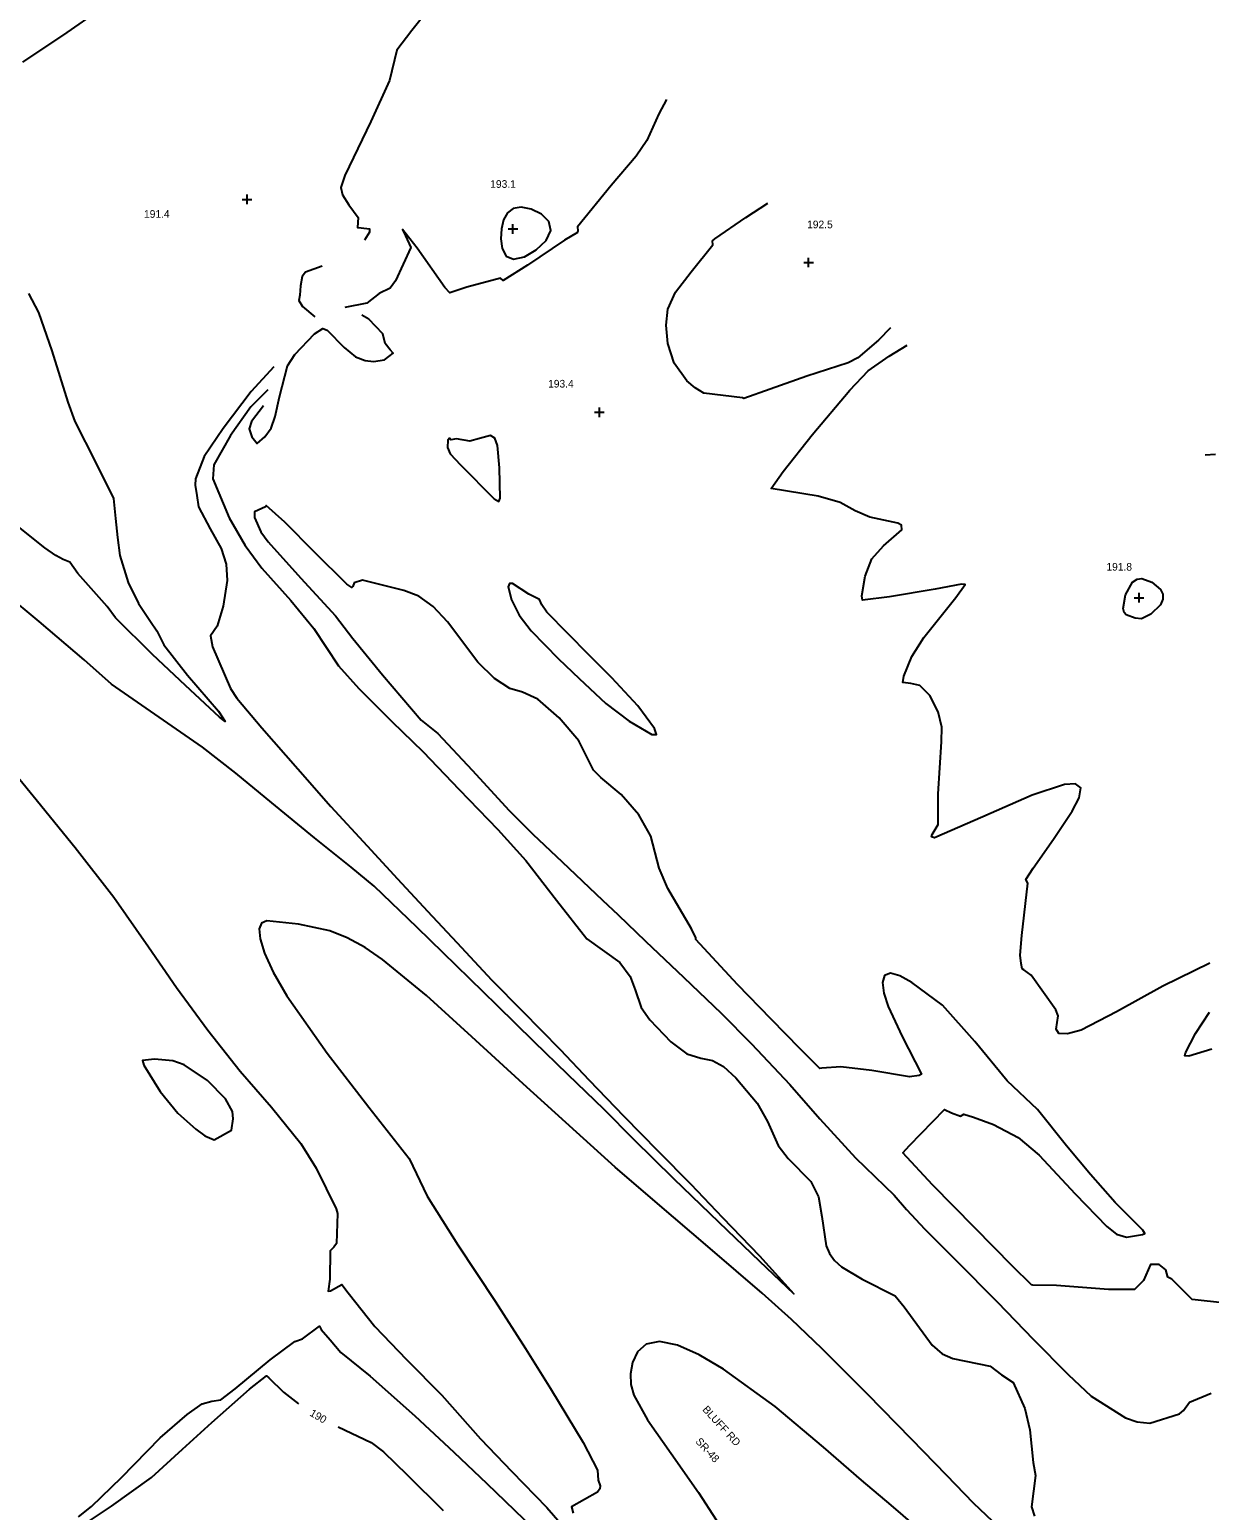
# Model space of a CAD drawing. Extents: x 1467615 to 2003689, y 770235 to 1108726.
# Drawn here: x 1993172.8 to 1993481.2, y 778593.3 to 778980.4 of the extents above; entities that cross this region are included whole.
import ezdxf

# ---------------------------------------------------------------- set-up
doc = ezdxf.new("R2010")
doc.units = 0
for name, color, linetype in [('RD_DTM_Major1', 7, 'Continuous'), ('RD_DTM_Major1_Lbl', 7, 'Continuous'), ('RD_DTM_Minor1', 7, 'Continuous'), ('RD_DTM_Spot_Elev', 7, 'Continuous'), ('RD_TX_Misc1', 7, 'Continuous')]:
    doc.layers.add(name, color=color, linetype=linetype)

msp = doc.modelspace()

# ---------------------------------------------------------------- linework, layer by layer
at = {"layer": 'RD_DTM_Major1'}
for points in [[(1993173.12, 778581.61), (1993173.53, 778581.29), (1993175, 778580.81), (1993176.87, 778581.73), (1993184.24, 778587.77), (1993194.16, 778594.39), (1993204.69, 778601.92), (1993212.78, 778609.32), (1993220.47, 778616.31), (1993230.25, 778624.96), (1993234.69, 778628.46), (1993235.3, 778627.97), (1993239.17, 778624.17), (1993243.06, 778621.19)], [(1993253.44, 778615.17), (1993262.05, 778611.04), (1993265.29, 778608.6), (1993271.49, 778602.6), (1993280.94, 778593.29)]]:
    msp.add_lwpolyline(points, dxfattribs=at)
at = {"layer": 'RD_DTM_Minor1'}
for points in [[(1993295.08, 779007.27), (1993289.19, 779000.76), (1993281.64, 778991.45), (1993272.68, 778980.2), (1993268.77, 778975.03), (1993266.89, 778967.06), (1993262.03, 778956.34), (1993255.22, 778942.29), (1993254.14, 778939.12), (1993254.57, 778937.24), (1993256.24, 778934.57), (1993258.68, 778931.32), (1993258.49, 778928.65), (1993259.44, 778928.58), (1993261.67, 778928.33), (1993261.61, 778927.48), (1993260.34, 778925.33)], [(1993190.82, 778985.39), (1993182.48, 778979.64), (1993170.94, 778971.86)], [(1993339.3, 778962.14), (1993337.27, 778958.41), (1993334.13, 778951.42), (1993331.37, 778947.36), (1993324.78, 778939.65), (1993315.99, 778928.85), (1993316.09, 778927.84), (1993315.98, 778927.35), (1993312.61, 778925.33), (1993302.98, 778918.79), (1993296.63, 778914.81), (1993295.86, 778915.4), (1993287.07, 778913.05), (1993282.66, 778911.57), (1993281.34, 778912.99), (1993274.13, 778923.25), (1993270.23, 778928.11), (1993271.04, 778926.47), (1993272.42, 778923.44), (1993268.42, 778914.72), (1993267.05, 778912.78), (1993264.21, 778911.39), (1993260.99, 778908.85), (1993255.16, 778907.74)], [(1993296.16, 778928.36), (1993295.99, 778925.7), (1993296.34, 778923.14), (1993297.39, 778921.2), (1993299.32, 778920.38), (1993302.14, 778921.02), (1993305.22, 778922.79), (1993307.8, 778925.23), (1993309.08, 778927.85), (1993308.52, 778930.23), (1993306.58, 778932.15), (1993303.94, 778933.46), (1993301.29, 778933.99), (1993299.19, 778933.65), (1993297.7, 778932.5), (1993296.71, 778930.7), (1993296.16, 778928.36)], [(1993397.82, 778902.42), (1993394.69, 778899.2), (1993389.34, 778894.6), (1993386.74, 778893.25), (1993375.99, 778889.83), (1993366.35, 778886.39), (1993359.49, 778883.97), (1993359.14, 778884.15), (1993349.09, 778885.39), (1993346.75, 778886.75), (1993344.59, 778888.6), (1993341.25, 778893.24), (1993339.62, 778898.32), (1993339.21, 778903.14), (1993339.61, 778907.33), (1993341.63, 778911.79), (1993345.72, 778917.1), (1993351.38, 778924.13), (1993351.28, 778925.17), (1993351.92, 778925.7), (1993360.03, 778931.32), (1993365.82, 778935.07)], [(1993249.31, 778918.55), (1993244.88, 778916.98), (1993244.04, 778915.88), (1993243.65, 778913.46), (1993243.39, 778910.95), (1993243.18, 778909.56), (1993244.1, 778908.01), (1993247.35, 778905.33)], [(1993172.52, 778911.39), (1993175.08, 778906.41), (1993178.63, 778896.45), (1993182.81, 778883.03), (1993184.58, 778877.93), (1993190.09, 778867.17), (1993194.73, 778857.81), (1993195.22, 778852.58), (1993195.8, 778847.6), (1993196.36, 778842.92), (1993198.53, 778835.91), (1993201.22, 778830.36), (1993204.43, 778825.63), (1993206.08, 778823.27), (1993207.91, 778819.54), (1993214.11, 778811.68), (1993222.13, 778802.19), (1993223.88, 778799.56), (1993222.4, 778800.67), (1993213.55, 778808.97), (1993204.9, 778817.05), (1993195.27, 778826.59), (1993193.1, 778829.56), (1993185.38, 778838.22), (1993183.31, 778841.21), (1993181.6, 778841.86), (1993179.65, 778842.89), (1993176.81, 778844.9), (1993166.87, 778852.9)], [(1993233.97, 778882.03), (1993230.8, 778877.98), (1993230.23, 778876.03), (1993230.92, 778873.91), (1993232.24, 778872.23), (1993234.32, 778873.94), (1993235.98, 778876.21), (1993236.95, 778879.25), (1993238.09, 778884.42), (1993240.18, 778892.51), (1993242.16, 778895.51), (1993247.26, 778900.83), (1993249.45, 778902.29), (1993250.61, 778901.84), (1993255.04, 778897.27), (1993257.97, 778894.84), (1993260.49, 778893.87), (1993262.69, 778893.67), (1993265.54, 778894.09), (1993267.85, 778895.82), (1993267.03, 778896.69), (1993265.71, 778898.38), (1993265.11, 778900.88), (1993261.45, 778904.67), (1993259.67, 778905.74)], [(1993481.37, 778736.34), (1993469.01, 778730.3), (1993456.9, 778723.59), (1993447.72, 778718.85), (1993444.1, 778717.84), (1993441.89, 778717.98), (1993441.12, 778719.11), (1993441.71, 778722.6), (1993441.09, 778724.16), (1993434.64, 778733.2), (1993432.67, 778734.58), (1993432.31, 778734.89), (1993432, 778736.3), (1993431.71, 778738.41), (1993432.16, 778743.61), (1993433.72, 778757.28), (1993433.22, 778758.22), (1993435.11, 778761.16), (1993440.45, 778768.79), (1993445.32, 778776.07), (1993447.14, 778779.6), (1993447.62, 778782.17), (1993446.25, 778783.27), (1993443.35, 778783.08), (1993434.91, 778780.29), (1993422.01, 778774.6), (1993409.31, 778769.13), (1993408.6, 778769.41), (1993408.73, 778770.02), (1993410.34, 778772.58), (1993410.34, 778780.6), (1993411.22, 778794.21), (1993411.3, 778798.06), (1993410.27, 778802.06), (1993408.1, 778806.37), (1993405.48, 778808.95), (1993403.13, 778809.46), (1993401.07, 778809.73), (1993401.35, 778811.37), (1993403.45, 778816.56), (1993406.55, 778821.49), (1993414.96, 778831.96), (1993417.33, 778835.34), (1993416.42, 778835.39), (1993409.56, 778834.16), (1993397.6, 778832.08), (1993390.49, 778831.26), (1993390.38, 778832.37), (1993391.2, 778837.5), (1993393, 778842.05), (1993396.04, 778845.49), (1993400.8, 778849.66), (1993400.76, 778850.89), (1993399.79, 778851.34), (1993392.43, 778852.91), (1993388.62, 778854.64), (1993384.69, 778856.8), (1993378.97, 778858.43), (1993366.68, 778860.4), (1993369.81, 778864.91), (1993377.34, 778874.43), (1993387.24, 778886.16), (1993392.02, 778891.16), (1993397.48, 778895.02), (1993402.21, 778897.93)], [(1993236.67, 778892.28), (1993230.74, 778885.8), (1993223.37, 778876.09), (1993218.39, 778868.77), (1993216.17, 778862.97), (1993216.04, 778861.3), (1993216.54, 778858.58), (1993216.92, 778855.67), (1993219.95, 778849.93), (1993222.86, 778844.79), (1993224.2, 778840.65), (1993224.42, 778836.4), (1993223.4, 778829.68), (1993221.8, 778824.48), (1993220.06, 778821.91), (1993220.64, 778819.05), (1993225.29, 778808.19), (1993226.94, 778805.67), (1993233.46, 778797.91), (1993242.89, 778787.16), (1993251.56, 778777.31), (1993261.07, 778767.02), (1993269, 778758.37), (1993276.83, 778749.93), (1993284.44, 778741.77), (1993293.66, 778731.91), (1993301.6, 778723.93), (1993311.53, 778713.77), (1993319.03, 778705.74), (1993328.12, 778696.38), (1993337.08, 778687.21), (1993345.69, 778678.54), (1993353.96, 778669.87), (1993363.61, 778659.85), (1993372.57, 778649.92), (1993363.66, 778658.36), (1993353.05, 778668.56), (1993341.22, 778679.99), (1993330.77, 778690.3), (1993322.96, 778698.1), (1993313.52, 778707.26), (1993304.73, 778715.75), (1993295.03, 778725.31), (1993284.33, 778735.77), (1993274.11, 778745.71), (1993262.89, 778756.46), (1993256.87, 778761.42), (1993247.25, 778769.16), (1993236.09, 778778.23), (1993226.71, 778786), (1993218, 778792.85), (1993204.38, 778802.24), (1993194.17, 778809.32), (1993187.04, 778815.67), (1993175.27, 778825.71), (1993166.46, 778833.03)], [(1993235.08, 778886.23), (1993230.65, 778881.8), (1993225.34, 778874.29), (1993220.98, 778866.6), (1993220.7, 778862.99), (1993224.97, 778852.75), (1993229.18, 778845.55), (1993233.53, 778839.58), (1993241.11, 778831.18), (1993247.07, 778823.81), (1993253.56, 778814.08), (1993258.87, 778808.16), (1993267.46, 778799.56), (1993275.66, 778791.56), (1993285.11, 778781.77), (1993295.23, 778771.29), (1993302.5, 778763.23), (1993310.51, 778752.83), (1993318.49, 778742.69), (1993327.06, 778736.54), (1993329.79, 778732.83), (1993331.08, 778729.42), (1993332.66, 778724.79), (1993334.92, 778721.56), (1993340.45, 778715.77), (1993344.64, 778712.67), (1993348.24, 778711.5), (1993351.32, 778710.94), (1993354.23, 778709.35), (1993357.45, 778706.38), (1993362.99, 778699.75), (1993365.68, 778694.98), (1993368.45, 778688.67), (1993371.09, 778685.32), (1993376.99, 778679.25), (1993378.99, 778675.3), (1993379.87, 778670.09), (1993381, 778662.47), (1993381.86, 778660.45), (1993383.18, 778658.63), (1993385.08, 778656.93), (1993390.48, 778653.79), (1993399.03, 778649.35), (1993401.43, 778646.54), (1993408.7, 778636.47), (1993411.32, 778634.25), (1993414.11, 778632.97), (1993423.92, 778631.01), (1993426.83, 778628.75), (1993429.89, 778626.77), (1993433, 778619.93), (1993434.24, 778614.34), (1993435.17, 778605.78), (1993435.73, 778602.39), (1993434.75, 778594.2), (1993435.53, 778591.76)], [(1993282.69, 778873.65), (1993282.14, 778873.04), (1993282.04, 778871.15), (1993282.77, 778869.53), (1993285.45, 778866.59), (1993294.22, 778857.75), (1993295.43, 778857.02), (1993295.77, 778857.88), (1993295.66, 778865.84), (1993295.14, 778871.71), (1993294.43, 778873.63), (1993293.29, 778874.33), (1993290.39, 778873.51), (1993287.89, 778872.81), (1993284.41, 778873.44), (1993282.89, 778873.19), (1993282.69, 778873.65)], [(1993480.1, 778869.23), (1993482.82, 778869.44)], [(1993485.43, 778647.43), (1993476.73, 778648.41), (1993471.43, 778653.74), (1993470.32, 778654.23), (1993469.86, 778656.17), (1993468.09, 778657.6), (1993465.78, 778657.6), (1993463.98, 778653.37), (1993461.62, 778651.06), (1993454.88, 778651.03), (1993441.27, 778652.09), (1993435.08, 778652.19), (1993434.7, 778652.25), (1993429.74, 778657.18), (1993419.86, 778667.18), (1993408.85, 778678.39), (1993401.03, 778686.78), (1993402.83, 778688.72), (1993411.93, 778698.13), (1993413.79, 778697.21), (1993416.18, 778696.35), (1993417, 778696.86), (1993419.58, 778696.1), (1993424.8, 778694.16), (1993431.2, 778690.79), (1993436.7, 778686.15), (1993446.11, 778676.04), (1993454.39, 778667.53), (1993456.92, 778665.47), (1993459.54, 778664.69), (1993463.74, 778665.4), (1993464.38, 778665.69), (1993463.79, 778666.55), (1993456.61, 778673.78), (1993450.16, 778681.13), (1993443.84, 778688.6), (1993436.29, 778698.1), (1993428.34, 778705.62), (1993419.88, 778715.84), (1993411.45, 778725.4), (1993403.46, 778731.27), (1993400.33, 778733.01), (1993397.81, 778733.78), (1993396.28, 778733.17), (1993395.76, 778731.33), (1993396.1, 778728.53), (1993397.21, 778725.03), (1993400.93, 778717.19), (1993405.93, 778707.38), (1993405.3, 778707), (1993402.8, 778706.6), (1993392.95, 778708.3), (1993384.87, 778709.22), (1993379.89, 778708.91), (1993379.37, 778708.86), (1993374.19, 778713.99), (1993366.67, 778721.73), (1993357.88, 778730.79), (1993346.92, 778742.52), (1993346.94, 778743.02), (1993345.81, 778745.34), (1993339.65, 778755.91), (1993337.37, 778761.23), (1993335.22, 778769.59), (1993332.02, 778775.13), (1993327.47, 778780.42), (1993322.08, 778784.93), (1993320.17, 778786.77), (1993316.35, 778794.44), (1993311.26, 778800.45), (1993305.66, 778805.36), (1993301.68, 778807.22), (1993298.35, 778808.17), (1993294.33, 778810.76), (1993289.97, 778815.06), (1993282.01, 778825.62), (1993278.29, 778829.62), (1993274.52, 778832.27), (1993270.63, 778833.79), (1993259.81, 778836.46), (1993257.61, 778835.74), (1993257.25, 778834.84), (1993256.99, 778834.52), (1993255.74, 778835.46), (1993247.26, 778843.82), (1993239.48, 778851.67), (1993234.63, 778855.98), (1993234.46, 778855.69), (1993231.56, 778854.32), (1993231.54, 778852.87), (1993233.21, 778849.15), (1993235.13, 778846.53), (1993243.67, 778836.98), (1993252.75, 778827.11), (1993257.29, 778821.27), (1993265.04, 778811.76), (1993275.19, 778799.92), (1993279.47, 778796.36), (1993288.49, 778786.81), (1993298.17, 778776.24), (1993304.34, 778770.07), (1993311.98, 778762.81), (1993322.59, 778752.82), (1993326.67, 778748.95)], [(1993316.42, 778810.76), (1993323.44, 778804.22), (1993329.56, 778799.59), (1993335.43, 778796.15), (1993336.67, 778796.13), (1993336.12, 778797.74), (1993331.77, 778803.6), (1993325, 778810.98), (1993318.99, 778816.99), (1993307.98, 778828.12), (1993306.72, 778830.05), (1993306.13, 778831.45), (1993304.49, 778832.21), (1993303.26, 778832.85), (1993299.06, 778835.6), (1993298.23, 778835.57), (1993297.94, 778834.72), (1993298.74, 778831.34), (1993300.78, 778827.31), (1993303.87, 778823.26), (1993311.09, 778815.89), (1993316.42, 778810.76)], [(1993458.65, 778829.1), (1993459.29, 778832.64), (1993461.1, 778835.96), (1993462.29, 778836.75), (1993463.57, 778836.94), (1993466.21, 778835.99), (1993468.43, 778834.04), (1993469.02, 778832.82), (1993469.04, 778831.47), (1993468.39, 778830.06), (1993465.91, 778827.55), (1993463.5, 778826.38), (1993461.82, 778826.56), (1993459.49, 778827.4), (1993458.92, 778828.02), (1993458.65, 778829.1)], [(1993164.78, 778791.01), (1993173.73, 778780.12), (1993184.67, 778766.58), (1993194.79, 778753.59), (1993203.87, 778740.6), (1993211.22, 778729.95), (1993219.39, 778718.83), (1993227.81, 778708.1), (1993235.99, 778698.72), (1993243.71, 778689.2), (1993247.69, 778682.79), (1993252.95, 778672.13), (1993253.28, 778670.94), (1993253.03, 778663.1), (1993252.31, 778662.15), (1993251.37, 778661.18), (1993251.3, 778653.78), (1993250.86, 778650.57), (1993251.49, 778650.73), (1993254.39, 778652.37), (1993256.11, 778650.16), (1993263.05, 778641.34), (1993271.29, 778632.73), (1993280.52, 778623.39), (1993290.65, 778612), (1993298.86, 778603.45), (1993308.04, 778594.05), (1993317.27, 778583.4)], [(1993424.63, 778590.37), (1993419.51, 778595.16), (1993412.55, 778602.4), (1993403.38, 778611.9), (1993391.85, 778623.71), (1993379.91, 778635.6), (1993371.95, 778643.21), (1993364.32, 778650.05), (1993350.72, 778661.73), (1993336.31, 778674.03), (1993325.91, 778683.05), (1993315.73, 778692.17), (1993301.84, 778704.8), (1993288.41, 778717.09), (1993276.54, 778727.88), (1993265.04, 778737.31), (1993260.47, 778740.44), (1993255.82, 778743.01), (1993251.29, 778744.8), (1993243.1, 778746.58), (1993234.83, 778747.38), (1993233.45, 778746.81), (1993232.82, 778745.35), (1993233.02, 778742.75), (1993234.17, 778738.97), (1993236.45, 778733.99), (1993240.01, 778727.81), (1993250.54, 778712.81), (1993261.5, 778698.73), (1993272, 778685.29), (1993276.7, 778675.44), (1993284.75, 778662.76), (1993294.52, 778647.97), (1993302.45, 778635.65), (1993308.98, 778625.13), (1993317.51, 778611.05), (1993321.27, 778603.86), (1993321.39, 778601.18), (1993321.94, 778599.68), (1993321.86, 778598.9), (1993321.22, 778598.1), (1993314.49, 778594.19), (1993314.88, 778592.57)], [(1993326.67, 778748.95), (1993333.84, 778742.07), (1993343.78, 778732.63), (1993353.57, 778723.27), (1993361.47, 778715.26), (1993371.55, 778704.67), (1993379.34, 778695.64), (1993388.67, 778685.5), (1993398.79, 778675.72), (1993402.03, 778671.99), (1993406.85, 778666.84), (1993414.88, 778658.83), (1993425.78, 778647.71), (1993435.11, 778638.08), (1993444.32, 778628.86), (1993450.35, 778623.16), (1993459.32, 778617.48), (1993462.3, 778616.47), (1993465.68, 778616.09), (1993473.36, 778618.54), (1993474.42, 778619.45), (1993476.02, 778621.61), (1993481.71, 778623.92)], [(1993481.88, 778713.89), (1993475.82, 778712.01), (1993474.82, 778712.13), (1993474.94, 778712.94), (1993477.56, 778717.96), (1993481.23, 778723.51)], [(1993218.6, 778691.25), (1993221, 778690.17), (1993225.58, 778692.71), (1993225.99, 778695.69), (1993225.86, 778697.62), (1993223.99, 778700.86), (1993219.27, 778705.65), (1993213.18, 778709.79), (1993210.27, 778710.84), (1993205.48, 778711.3), (1993202.28, 778710.87), (1993202.66, 778709.65), (1993206.93, 778702.78), (1993211.57, 778697.14), (1993216.26, 778692.94), (1993218.6, 778691.25)], [(1993185.6, 778591.63), (1993188.93, 778594.28), (1993196.84, 778601.94), (1993206.89, 778612.31), (1993213.98, 778618.39), (1993217.94, 778621.17), (1993220.39, 778621.87), (1993222.76, 778622.18), (1993226.53, 778625.11), (1993235.68, 778632.65), (1993242.1, 778637.43), (1993244.17, 778638.11), (1993248.6, 778641.5), (1993249, 778640.63), (1993251.32, 778637.93), (1993254.13, 778634.62), (1993261.8, 778628.41), (1993273.51, 778618.04), (1993283.7, 778608.56), (1993292.3, 778600.3), (1993304.32, 778588.77)], [(1993410.57, 778583.82), (1993398.04, 778594.64), (1993390.26, 778601.23), (1993380.3, 778609.86), (1993367.71, 778620.44), (1993354.23, 778630.22), (1993347.85, 778633.94), (1993342.14, 778636.46), (1993337.44, 778637.46), (1993334, 778636.76), (1993331.71, 778634.75), (1993330.4, 778631.98), (1993329.88, 778628.99), (1993330, 778626.19), (1993330.76, 778623.43), (1993334.35, 778616.99), (1993340.54, 778608.15), (1993347.69, 778597.99), (1993356.85, 778583.66)]]:
    msp.add_lwpolyline(points, dxfattribs=at)
at = {"layer": 'RD_DTM_Spot_Elev'}
for p, q in [((1993228.38, 778936.02), (1993230.88, 778936.02)), ((1993229.63, 778934.77), (1993229.63, 778937.27)), ((1993297.89, 778928.29), (1993300.39, 778928.29)), ((1993299.14, 778927.04), (1993299.14, 778929.54)), ((1993376.43, 778918.28), (1993376.43, 778920.78)), ((1993375.18, 778919.53), (1993377.68, 778919.53)), ((1993321.73, 778879.12), (1993321.73, 778881.62)), ((1993320.48, 778880.37), (1993322.98, 778880.37)), ((1993461.58, 778831.89), (1993464.08, 778831.89)), ((1993462.83, 778830.64), (1993462.83, 778833.14))]:
    msp.add_line(p, q, dxfattribs=at)

# ---------------------------------------------------------------- texts
at = {"layer": 'RD_DTM_Major1_Lbl'}
msp.add_text('190', height=2, rotation=329.9821, dxfattribs=at).set_placement((1993245.83, 778618.18))
at = {"layer": 'RD_DTM_Spot_Elev'}
for s, p in [('193.1', (1993293.21, 778939.04)), ('191.4', (1993202.7, 778931.21)), ('192.5', (1993376.05, 778928.47)), ('193.4', (1993308.34, 778886.83)), ('191.8', (1993454.29, 778838.97))]:
    msp.add_text(s, height=2, dxfattribs=at).set_placement(p)
at = {"layer": 'RD_TX_Misc1'}
for s, rotation, p in [('BLUFF RD', 312.4362, (1993348.55, 778619.55)), ('SR-48', 312.436, (1993346.73, 778611.2))]:
    msp.add_text(s, height=2, rotation=rotation, dxfattribs=at).set_placement(p)

doc.saveas('drawing.dxf')
